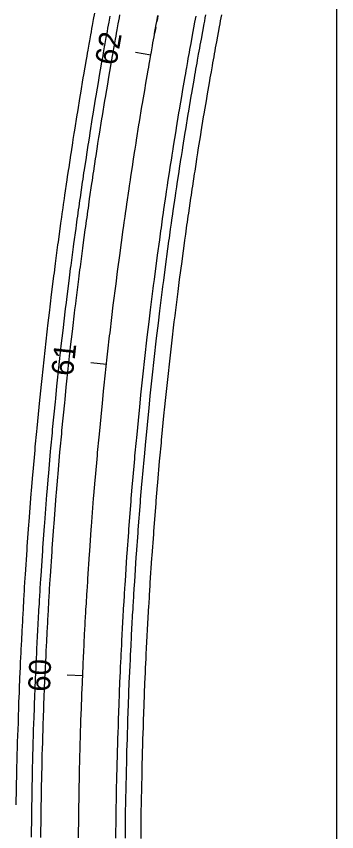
# Model space of a CAD drawing. Extents: x 2318076 to 2324211, y 613525 to 630327.
# Drawn here: x 2318594.2 to 2318696.7, y 620852.4 to 621113.3 of the extents above; entities that cross this region are included whole.
import ezdxf

# ---------------------------------------------------------------- set-up
doc = ezdxf.new("R2010")
doc.units = 0
for name, color, linetype in [('GE_P_CL_50', 7, 'Continuous'), ('PV_P_EOP', 7, 'Continuous'), ('PV_P_Shoulder', 7, 'Continuous'), ('RD_X_GR_Lt', 7, 'Continuous'), ('RD_X_GR_Rt', 7, 'Continuous'), ('SC_Scratch3', 7, 'Continuous')]:
    doc.layers.add(name, color=color, linetype=linetype)

msp = doc.modelspace()

# ---------------------------------------------------------------- linework, layer by layer
at = {"layer": 'GE_P_CL_50'}
for p, q in [((2318637.23, 621100.93), (2318632.3, 621101.8)), ((2318623.06, 621001.95), (2318618.09, 621002.5)), ((2318615.45, 620902.26), (2318610.45, 620902.47))]:
    msp.add_line(p, q, dxfattribs=at)
msp.add_lwpolyline([(2318614.1, 620850.47), (2318614.18, 620857.38), (2318614.19, 620858.37), (2318614.43, 620871.21), (2318614.45, 620872.19), (2318614.52, 620875.16), (2318614.55, 620876.14), (2318614.63, 620879.11), (2318614.65, 620880.09), (2318614.74, 620883.06), (2318614.77, 620884.04), (2318614.87, 620887), (2318614.9, 620887.99), (2318615.04, 620891.94), (2318615.07, 620892.93), (2318615.15, 620894.9), (2318615.19, 620895.89), (2318615.22, 620896.87), (2318615.26, 620897.86), (2318615.47, 620902.8), (2318615.51, 620903.78), (2318615.56, 620904.77), (2318615.6, 620905.76), (2318615.74, 620908.72), (2318615.79, 620909.7), (2318615.93, 620912.66), (2318615.98, 620913.65), (2318616.03, 620914.64), (2318616.08, 620915.62), (2318616.24, 620918.58), (2318616.29, 620919.57), (2318616.46, 620922.53), (2318616.51, 620923.51), (2318616.57, 620924.5), (2318616.63, 620925.48), (2318616.8, 620928.44), (2318616.86, 620929.43), (2318617.05, 620932.39), (2318617.11, 620933.37), (2318617.64, 620941.26), (2318617.7, 620942.24), (2318618.2, 620949.14), (2318618.27, 620950.12), (2318618.96, 620958.99), (2318619.04, 620959.97), (2318619.45, 620964.89), (2318619.54, 620965.88), (2318620.14, 620972.76), (2318620.23, 620973.75), (2318620.68, 620978.66), (2318620.78, 620979.65), (2318621.64, 620988.5), (2318621.74, 620989.48), (2318622.14, 620993.41), (2318622.25, 620994.39), (2318622.77, 620999.3), (2318622.87, 621000.28), (2318623.41, 621005.19), (2318623.52, 621006.17), (2318624.08, 621011.08), (2318624.2, 621012.06), (2318624.78, 621016.97), (2318624.9, 621017.95), (2318625.13, 621019.91), (2318625.25, 621020.89), (2318626.11, 621027.75), (2318626.23, 621028.73), (2318626.48, 621030.69), (2318626.61, 621031.67), (2318627.39, 621037.54), (2318627.52, 621038.52), (2318628.18, 621043.42), (2318628.32, 621044.4), (2318628.59, 621046.35), (2318628.73, 621047.33), (2318629, 621049.29), (2318629.14, 621050.26), (2318629.42, 621052.22), (2318629.56, 621053.2), (2318630.27, 621058.08), (2318630.42, 621059.06), (2318630.71, 621061.02), (2318630.86, 621061.99), (2318631.45, 621065.9), (2318631.6, 621066.87), (2318632.05, 621069.8), (2318632.2, 621070.78), (2318632.51, 621072.73), (2318632.66, 621073.71), (2318633.44, 621078.58), (2318633.6, 621079.56), (2318634.4, 621084.43), (2318634.56, 621085.41), (2318635.38, 621090.28), (2318635.55, 621091.25), (2318636.38, 621096.12), (2318636.55, 621097.09), (2318636.72, 621098.06), (2318636.89, 621099.04), (2318637.24, 621100.98), (2318637.41, 621101.95), (2318637.76, 621103.9), (2318637.93, 621104.87), (2318638.11, 621105.84), (2318638.28, 621106.81), (2318638.64, 621108.76), (2318638.81, 621109.73), (2318638.64, 621108.76), (2318638.46, 621107.79), (2318638.99, 621110.7), (2318639.17, 621111.67), (2318639.35, 621112.64), (2318639.53, 621113.61), (2318639.35, 621112.64), (2318639.17, 621111.67), (2318639.53, 621113.61)], dxfattribs=at)
at = {"layer": 'PV_P_EOP'}
for points in [[(2318602.1, 620850.59), (2318602.18, 620857.53), (2318602.19, 620858.56), (2318602.43, 620871.45), (2318602.45, 620872.48), (2318602.52, 620875.46), (2318602.55, 620876.46), (2318602.63, 620879.44), (2318602.66, 620880.44), (2318602.75, 620883.42), (2318602.78, 620884.42), (2318602.87, 620887.4), (2318602.91, 620888.4), (2318603.04, 620892.37), (2318603.08, 620893.37), (2318603.16, 620895.36), (2318603.19, 620896.36), (2318603.23, 620897.35), (2318603.27, 620898.35), (2318603.48, 620903.31), (2318603.53, 620904.31), (2318603.57, 620905.31), (2318603.62, 620906.31), (2318603.75, 620909.28), (2318603.8, 620910.28), (2318603.95, 620913.26), (2318604, 620914.26), (2318604.05, 620915.25), (2318604.1, 620916.25), (2318604.26, 620919.22), (2318604.31, 620920.23), (2318604.48, 620923.2), (2318604.53, 620924.2), (2318604.59, 620925.19), (2318604.65, 620926.19), (2318604.83, 620929.16), (2318604.89, 620930.16), (2318605.07, 620933.14), (2318605.14, 620934.15), (2318605.66, 620942.07), (2318605.73, 620943.09), (2318606.23, 620950.01), (2318606.31, 620951.03), (2318607, 620959.94), (2318607.08, 620960.95), (2318607.5, 620965.9), (2318607.58, 620966.91), (2318608.19, 620973.83), (2318608.28, 620974.84), (2318608.74, 620979.78), (2318608.83, 620980.79), (2318609.7, 620989.68), (2318609.8, 620990.69), (2318610.21, 620994.64), (2318610.31, 620995.65), (2318610.84, 621000.58), (2318610.94, 621001.59), (2318611.49, 621006.52), (2318611.6, 621007.52), (2318612.16, 621012.45), (2318612.28, 621013.46), (2318612.86, 621018.39), (2318612.98, 621019.38), (2318613.22, 621021.36), (2318613.34, 621022.36), (2318614.2, 621029.25), (2318614.33, 621030.25), (2318614.58, 621032.22), (2318614.71, 621033.22), (2318615.49, 621039.12), (2318615.62, 621040.13), (2318616.29, 621045.05), (2318616.43, 621046.04), (2318616.7, 621048.01), (2318616.84, 621049), (2318617.12, 621050.97), (2318617.26, 621051.96), (2318617.54, 621053.92), (2318617.68, 621054.92), (2318618.4, 621059.83), (2318618.55, 621060.82), (2318618.84, 621062.79), (2318618.99, 621063.78), (2318619.59, 621067.71), (2318619.74, 621068.7), (2318620.19, 621071.64), (2318620.35, 621072.63), (2318620.66, 621074.6), (2318620.81, 621075.59), (2318621.6, 621080.49), (2318621.76, 621081.49), (2318622.56, 621086.38), (2318622.73, 621087.38), (2318623.55, 621092.28), (2318623.72, 621093.27), (2318624.56, 621098.16), (2318624.73, 621099.15), (2318624.9, 621100.13), (2318625.08, 621101.11), (2318625.42, 621103.07), (2318625.6, 621104.06), (2318625.95, 621106.01), (2318626.12, 621106.99), (2318626.3, 621107.97), (2318626.48, 621108.96), (2318626.83, 621110.91), (2318627.19, 621112.87), (2318627.37, 621113.85)], [(2318650.44, 621106.61), (2318651.33, 621111.42), (2318651.51, 621112.38), (2318651.69, 621113.35)], [(2318626.1, 620850.35), (2318626.18, 620857.23), (2318626.19, 620858.18), (2318626.42, 620870.96), (2318626.45, 620871.91), (2318626.52, 620874.86), (2318626.54, 620875.83), (2318626.62, 620878.78), (2318626.65, 620879.75), (2318626.74, 620882.69), (2318626.77, 620883.67), (2318626.86, 620886.61), (2318626.89, 620887.58), (2318627.03, 620891.51), (2318627.07, 620892.48), (2318627.14, 620894.44), (2318627.18, 620895.42), (2318627.22, 620896.4), (2318627.25, 620897.37), (2318627.46, 620902.28), (2318627.5, 620903.25), (2318627.55, 620904.23), (2318627.59, 620905.21), (2318627.73, 620908.15), (2318627.77, 620909.12), (2318627.92, 620912.07), (2318627.97, 620913.04), (2318628.02, 620914.02), (2318628.07, 620914.99), (2318628.22, 620917.94), (2318628.28, 620918.91), (2318628.44, 620921.85), (2318628.49, 620922.83), (2318628.55, 620923.8), (2318628.61, 620924.78), (2318628.78, 620927.72), (2318628.84, 620928.69), (2318629.03, 620931.63), (2318629.09, 620932.59), (2318629.61, 620940.44), (2318629.67, 620941.39), (2318630.17, 620948.26), (2318630.24, 620949.21), (2318630.93, 620958.03), (2318631, 620958.99), (2318631.41, 620963.88), (2318631.49, 620964.84), (2318632.09, 620971.7), (2318632.18, 620972.65), (2318632.63, 620977.55), (2318632.72, 620978.5), (2318633.58, 620987.31), (2318633.68, 620988.26), (2318634.08, 620992.17), (2318634.18, 620993.14), (2318634.7, 620998.02), (2318634.8, 620998.98), (2318635.34, 621003.87), (2318635.45, 621004.83), (2318636.01, 621009.71), (2318636.12, 621010.67), (2318636.69, 621015.55), (2318636.81, 621016.51), (2318637.05, 621018.46), (2318637.16, 621019.42), (2318638.01, 621026.25), (2318638.14, 621027.21), (2318638.39, 621029.16), (2318638.51, 621030.12), (2318639.28, 621035.96), (2318639.41, 621036.92), (2318640.07, 621041.79), (2318640.2, 621042.75), (2318640.47, 621044.69), (2318640.61, 621045.66), (2318640.88, 621047.61), (2318641.02, 621048.57), (2318641.3, 621050.52), (2318641.44, 621051.48), (2318642.15, 621056.34), (2318642.29, 621057.3), (2318642.58, 621059.24), (2318642.72, 621060.2), (2318643.31, 621064.09), (2318643.46, 621065.05), (2318643.91, 621067.96), (2318644.06, 621068.92), (2318644.36, 621070.86), (2318644.52, 621071.82), (2318645.29, 621076.67), (2318645.45, 621077.63), (2318646.24, 621082.48), (2318646.4, 621083.43), (2318647.21, 621088.28), (2318647.38, 621089.23), (2318648.21, 621094.07), (2318648.38, 621095.03), (2318648.54, 621095.99), (2318648.71, 621096.96), (2318649.05, 621098.89), (2318649.23, 621099.85), (2318649.57, 621101.78), (2318649.74, 621102.75), (2318649.92, 621103.71), (2318650.09, 621104.67), (2318650.44, 621106.61)]]:
    msp.add_lwpolyline(points, dxfattribs=at)
at = {"layer": 'PV_P_Shoulder'}
for points in [[(2318653.39, 621106.06), (2318654.28, 621110.88), (2318654.46, 621111.83), (2318654.64, 621112.8), (2318654.82, 621113.76)], [(2318599.1, 620850.62), (2318599.18, 620857.57), (2318599.19, 620858.61), (2318599.43, 620871.52), (2318599.45, 620872.55), (2318599.53, 620875.53), (2318599.55, 620876.54), (2318599.63, 620879.52), (2318599.66, 620880.53), (2318599.75, 620883.51), (2318599.78, 620884.51), (2318599.87, 620887.5), (2318599.91, 620888.5), (2318600.05, 620892.48), (2318600.08, 620893.48), (2318600.16, 620895.47), (2318600.2, 620896.47), (2318600.24, 620897.47), (2318600.28, 620898.48), (2318600.48, 620903.44), (2318600.53, 620904.45), (2318600.57, 620905.44), (2318600.62, 620906.44), (2318600.76, 620909.42), (2318600.8, 620910.43), (2318600.95, 620913.41), (2318601, 620914.41), (2318601.05, 620915.41), (2318601.1, 620916.41), (2318601.26, 620919.38), (2318601.32, 620920.39), (2318601.48, 620923.37), (2318601.54, 620924.37), (2318601.6, 620925.37), (2318601.65, 620926.37), (2318601.83, 620929.34), (2318601.89, 620930.35), (2318602.08, 620933.33), (2318602.14, 620934.34), (2318602.67, 620942.27), (2318602.74, 620943.3), (2318603.24, 620950.23), (2318603.32, 620951.26), (2318604.01, 620960.17), (2318604.09, 620961.2), (2318604.51, 620966.15), (2318604.59, 620967.17), (2318605.2, 620974.09), (2318605.29, 620975.11), (2318605.75, 620980.06), (2318605.85, 620981.08), (2318606.71, 620989.98), (2318606.82, 620991), (2318607.22, 620994.95), (2318607.33, 620995.96), (2318607.85, 621000.9), (2318607.96, 621001.91), (2318608.51, 621006.85), (2318608.62, 621007.86), (2318609.18, 621012.8), (2318609.3, 621013.81), (2318609.88, 621018.74), (2318610, 621019.74), (2318610.24, 621021.72), (2318610.37, 621022.73), (2318611.23, 621029.63), (2318611.35, 621030.63), (2318611.61, 621032.61), (2318611.74, 621033.61), (2318612.52, 621039.52), (2318612.65, 621040.53), (2318613.32, 621045.45), (2318613.46, 621046.45), (2318613.73, 621048.42), (2318613.87, 621049.42), (2318614.15, 621051.39), (2318614.29, 621052.38), (2318614.57, 621054.35), (2318614.72, 621055.35), (2318615.43, 621060.27), (2318615.58, 621061.26), (2318615.87, 621063.23), (2318616.02, 621064.23), (2318616.62, 621068.16), (2318616.77, 621069.16), (2318617.23, 621072.1), (2318617.38, 621073.1), (2318617.69, 621075.06), (2318617.85, 621076.06), (2318618.63, 621080.97), (2318618.8, 621081.97), (2318619.6, 621086.87), (2318619.77, 621087.88), (2318620.59, 621092.78), (2318620.76, 621093.78), (2318621.6, 621098.67), (2318621.78, 621099.67), (2318621.95, 621100.65), (2318622.12, 621101.63), (2318622.47, 621103.59), (2318622.64, 621104.58), (2318622.99, 621106.54), (2318623.17, 621107.52), (2318623.35, 621108.51), (2318623.52, 621109.49), (2318623.88, 621111.45), (2318624.24, 621113.41)], [(2318629.1, 620850.32), (2318629.18, 620857.19), (2318629.19, 620858.13), (2318629.42, 620870.9), (2318629.44, 620871.84), (2318629.52, 620874.78), (2318629.54, 620875.75), (2318629.62, 620878.69), (2318629.65, 620879.66), (2318629.73, 620882.6), (2318629.76, 620883.57), (2318629.86, 620886.51), (2318629.89, 620887.48), (2318630.03, 620891.4), (2318630.06, 620892.37), (2318630.14, 620894.33), (2318630.17, 620895.3), (2318630.21, 620896.28), (2318630.25, 620897.25), (2318630.46, 620902.15), (2318630.5, 620903.12), (2318630.54, 620904.1), (2318630.59, 620905.07), (2318630.72, 620908.01), (2318630.77, 620908.98), (2318630.91, 620911.92), (2318630.96, 620912.89), (2318631.01, 620913.87), (2318631.06, 620914.84), (2318631.22, 620917.78), (2318631.27, 620918.74), (2318631.43, 620921.68), (2318631.49, 620922.65), (2318631.55, 620923.63), (2318631.6, 620924.6), (2318631.78, 620927.54), (2318631.84, 620928.51), (2318632.02, 620931.45), (2318632.08, 620932.4), (2318632.6, 620940.24), (2318632.67, 620941.18), (2318633.16, 620948.04), (2318633.23, 620948.98), (2318633.92, 620957.8), (2318633.99, 620958.74), (2318634.4, 620963.63), (2318634.48, 620964.58), (2318635.08, 620971.43), (2318635.17, 620972.38), (2318635.62, 620977.27), (2318635.71, 620978.21), (2318636.57, 620987.01), (2318636.66, 620987.96), (2318637.06, 620991.87), (2318637.16, 620992.82), (2318637.68, 620997.7), (2318637.79, 620998.66), (2318638.32, 621003.54), (2318638.43, 621004.49), (2318638.99, 621009.37), (2318639.1, 621010.32), (2318639.67, 621015.19), (2318639.79, 621016.15), (2318640.02, 621018.1), (2318640.14, 621019.05), (2318640.99, 621025.87), (2318641.11, 621026.83), (2318641.36, 621028.77), (2318641.49, 621029.73), (2318642.25, 621035.57), (2318642.38, 621036.52), (2318643.04, 621041.38), (2318643.17, 621042.34), (2318643.44, 621044.28), (2318643.58, 621045.24), (2318643.85, 621047.18), (2318643.99, 621048.15), (2318644.27, 621050.09), (2318644.41, 621051.05), (2318645.11, 621055.9), (2318645.26, 621056.86), (2318645.54, 621058.8), (2318645.69, 621059.75), (2318646.28, 621063.64), (2318646.42, 621064.59), (2318646.87, 621067.5), (2318647.02, 621068.46), (2318647.33, 621070.4), (2318647.48, 621071.35), (2318648.25, 621076.2), (2318648.41, 621077.14), (2318649.2, 621081.99), (2318649.36, 621082.93), (2318650.17, 621087.78), (2318650.33, 621088.72), (2318651.17, 621093.56), (2318651.33, 621094.51), (2318651.5, 621095.48), (2318651.67, 621096.44), (2318652.01, 621098.37), (2318652.18, 621099.33), (2318652.52, 621101.26), (2318652.7, 621102.22), (2318652.87, 621103.18), (2318653.04, 621104.14), (2318653.39, 621106.07)]]:
    msp.add_lwpolyline(points, dxfattribs=at)
at = {"layer": 'RD_X_GR_Lt'}
msp.add_lwpolyline([(2318594.23, 620860.98), (2318594.43, 620871.62), (2318594.45, 620872.67), (2318594.53, 620875.65), (2318594.55, 620876.67), (2318594.63, 620879.66), (2318594.66, 620880.67), (2318594.75, 620883.66), (2318594.78, 620884.67), (2318594.88, 620887.66), (2318594.91, 620888.68), (2318595.05, 620892.66), (2318595.09, 620893.67), (2318595.16, 620895.66), (2318595.2, 620896.67), (2318595.24, 620897.67), (2318595.28, 620898.68), (2318595.49, 620903.65), (2318595.53, 620904.67), (2318595.58, 620905.67), (2318595.62, 620906.67), (2318595.76, 620909.66), (2318595.81, 620910.67), (2318595.96, 620913.66), (2318596.01, 620914.66), (2318596.06, 620915.66), (2318596.11, 620916.67), (2318596.27, 620919.65), (2318596.32, 620920.67), (2318596.49, 620923.65), (2318596.55, 620924.66), (2318596.6, 620925.65), (2318596.66, 620926.66), (2318596.84, 620929.64), (2318596.9, 620930.66), (2318597.09, 620933.64), (2318597.15, 620934.67), (2318597.68, 620942.61), (2318597.75, 620943.65), (2318598.25, 620950.6), (2318598.33, 620951.64), (2318599.03, 620960.57), (2318599.11, 620961.61), (2318599.52, 620966.57), (2318599.61, 620967.6), (2318600.22, 620974.54), (2318600.31, 620975.57), (2318600.77, 620980.52), (2318600.87, 620981.56), (2318601.74, 620990.47), (2318601.84, 620991.5), (2318602.25, 620995.47), (2318602.36, 620996.48), (2318602.88, 621001.43), (2318602.99, 621002.45), (2318603.54, 621007.4), (2318603.65, 621008.42), (2318604.22, 621013.37), (2318604.33, 621014.39), (2318604.92, 621019.33), (2318605.04, 621020.34), (2318605.28, 621022.32), (2318605.4, 621023.34), (2318606.27, 621030.25), (2318606.39, 621031.27), (2318606.65, 621033.25), (2318606.78, 621034.26), (2318607.56, 621040.18), (2318607.7, 621041.2), (2318608.37, 621046.13), (2318608.51, 621047.14), (2318608.78, 621049.11), (2318608.92, 621050.11), (2318609.2, 621052.09), (2318609.34, 621053.09), (2318609.62, 621055.06), (2318609.77, 621056.07), (2318610.49, 621060.99), (2318610.64, 621062), (2318610.93, 621063.97), (2318611.08, 621064.97), (2318611.68, 621068.91), (2318611.83, 621069.92), (2318612.29, 621072.87), (2318612.44, 621073.87), (2318612.75, 621075.84), (2318612.91, 621076.85), (2318613.7, 621081.76), (2318613.86, 621082.78), (2318614.67, 621087.69), (2318614.84, 621088.7), (2318615.66, 621093.61), (2318615.83, 621094.62), (2318616.68, 621099.53), (2318616.85, 621100.53), (2318617.02, 621101.51), (2318617.2, 621102.5), (2318617.54, 621104.47), (2318617.72, 621105.46), (2318618.07, 621107.42), (2318618.25, 621108.41), (2318618.43, 621109.39), (2318618.6, 621110.38), (2318618.96, 621112.35), (2318619.32, 621114.31)], dxfattribs=at)
at = {"layer": 'RD_X_GR_Rt'}
for points in [[(2318658.31, 621105.16), (2318659.2, 621109.97), (2318659.37, 621110.92), (2318659.55, 621111.88), (2318659.73, 621112.83), (2318659.91, 621113.79)], [(2318634.1, 620850.27), (2318634.18, 620857.13), (2318634.19, 620858.05), (2318634.42, 620870.79), (2318634.44, 620871.72), (2318634.51, 620874.66), (2318634.54, 620875.62), (2318634.62, 620878.56), (2318634.64, 620879.52), (2318634.73, 620882.45), (2318634.76, 620883.41), (2318634.86, 620886.35), (2318634.89, 620887.31), (2318635.02, 620891.22), (2318635.06, 620892.18), (2318635.13, 620894.14), (2318635.17, 620895.11), (2318635.21, 620896.08), (2318635.25, 620897.04), (2318635.45, 620901.94), (2318635.49, 620902.9), (2318635.54, 620903.87), (2318635.58, 620904.84), (2318635.72, 620907.78), (2318635.76, 620908.74), (2318635.91, 620911.67), (2318635.96, 620912.64), (2318636.01, 620913.61), (2318636.06, 620914.58), (2318636.21, 620917.51), (2318636.26, 620918.47), (2318636.43, 620921.4), (2318636.48, 620922.37), (2318636.54, 620923.34), (2318636.59, 620924.31), (2318636.77, 620927.24), (2318636.83, 620928.2), (2318637.01, 620931.13), (2318637.07, 620932.07), (2318637.59, 620939.9), (2318637.65, 620940.83), (2318638.15, 620947.68), (2318638.22, 620948.6), (2318638.9, 620957.4), (2318638.98, 620958.33), (2318639.38, 620963.21), (2318639.46, 620964.15), (2318640.06, 620970.99), (2318640.15, 620971.93), (2318640.6, 620976.81), (2318640.69, 620977.74), (2318641.54, 620986.52), (2318641.64, 620987.45), (2318642.04, 620991.35), (2318642.14, 620992.3), (2318642.65, 620997.17), (2318642.76, 620998.11), (2318643.29, 621002.98), (2318643.4, 621003.93), (2318643.95, 621008.79), (2318644.06, 621009.74), (2318644.64, 621014.6), (2318644.75, 621015.55), (2318644.99, 621017.49), (2318645.1, 621018.44), (2318645.95, 621025.25), (2318646.07, 621026.19), (2318646.32, 621028.13), (2318646.44, 621029.08), (2318647.21, 621034.91), (2318647.34, 621035.85), (2318648, 621040.7), (2318648.13, 621041.65), (2318648.4, 621043.59), (2318648.53, 621044.55), (2318648.8, 621046.48), (2318648.94, 621047.44), (2318649.22, 621049.38), (2318649.35, 621050.33), (2318650.06, 621055.18), (2318650.2, 621056.12), (2318650.49, 621058.06), (2318650.63, 621059.01), (2318651.22, 621062.88), (2318651.37, 621063.83), (2318651.81, 621066.73), (2318651.96, 621067.69), (2318652.27, 621069.62), (2318652.42, 621070.57), (2318653.19, 621075.4), (2318653.34, 621076.34), (2318654.13, 621081.17), (2318654.29, 621082.11), (2318655.1, 621086.94), (2318655.26, 621087.88), (2318656.09, 621092.71), (2318656.26, 621093.65), (2318656.42, 621094.61), (2318656.59, 621095.57), (2318656.93, 621097.5), (2318657.1, 621098.45), (2318657.45, 621100.37), (2318657.62, 621101.33), (2318657.79, 621102.29), (2318657.96, 621103.25), (2318658.31, 621105.17)]]:
    msp.add_lwpolyline(points, dxfattribs=at)
at = {"layer": 'SC_Scratch3'}
msp.add_line((2318696.66, 614778.41), (2318696.66, 630327.22), dxfattribs=at)

# ---------------------------------------------------------------- texts
at = {"layer": 'GE_P_CL_50'}
for s, rotation, p in [('62', 79.9935, (2318626.19, 621097.39)), ('61', 83.7134, (2318612.31, 620998.02)), ('60', 87.6014, (2318604.97, 620897.12))]:
    msp.add_text(s, height=7, rotation=rotation, dxfattribs=at).set_placement(p)

doc.saveas('drawing.dxf')
